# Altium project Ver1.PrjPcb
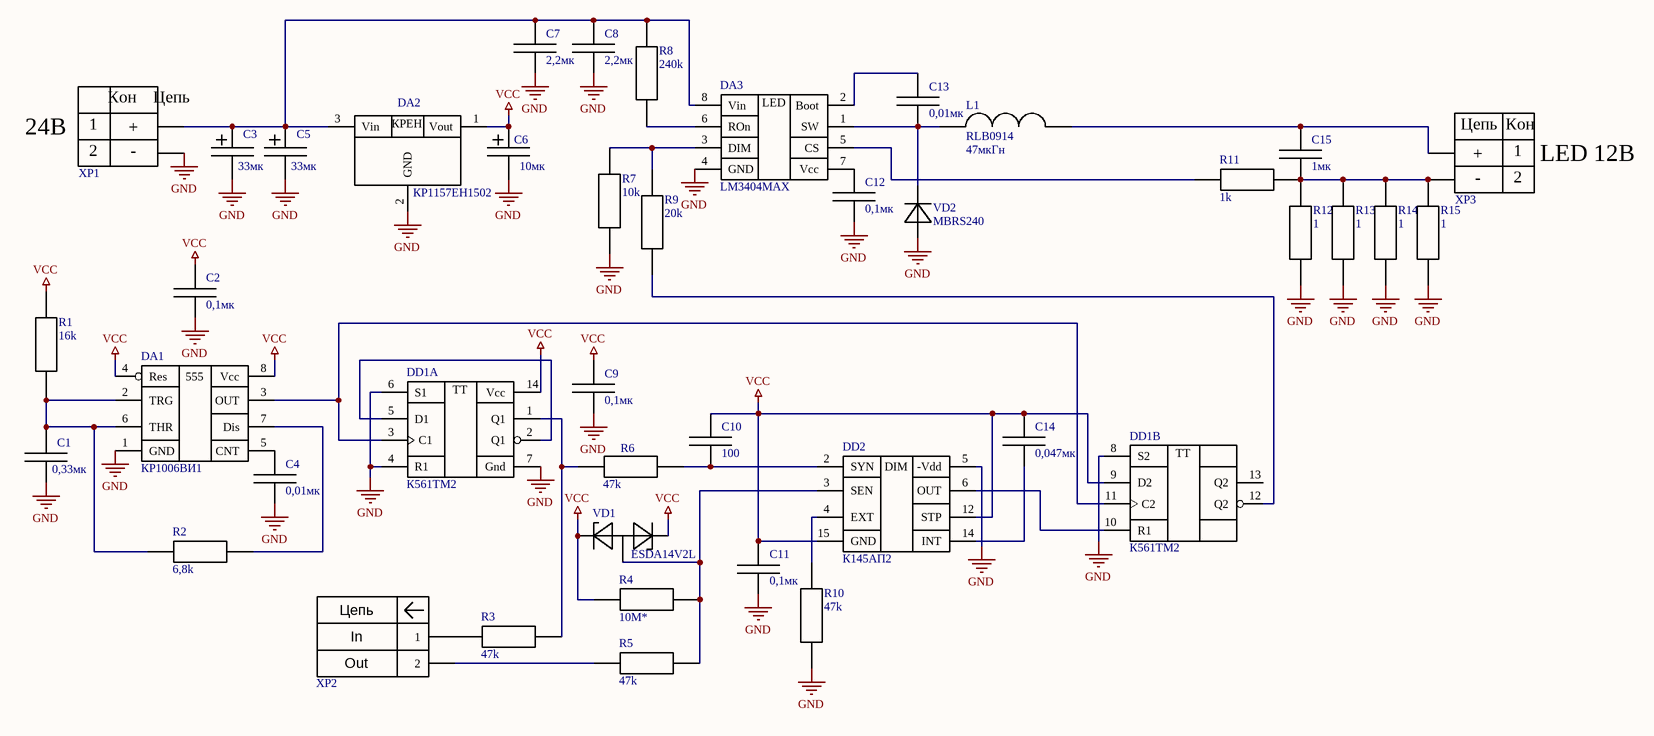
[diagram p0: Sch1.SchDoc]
1 sheet, 41 parts. Net scope: global (net labels, ports and power ports of the same name join across sheets).
Board file: PCB1.PcbDoc

## Sheet Sch1.SchDoc: Наименование
size 420 x 297 mm; ApprovedBy: Утвердил; CheckedBy: Проверил; Author: Разработал; CompanyName: Организация; DocumentNumber: Обозначение; SheetNumber: Лист; SheetTotal: Листов; TechContr: Техн.контр.; NormCotr: Нормоконтроль; DocumentType: Тип документа; InvNumOrigin: Инв № подл; InvNumDuplicate: Инв № дубл; InsteadOfInvNum: Взам. инв. №; RefNumber: Справ. №; InitialUsage: Перв. примен.; Lit: О

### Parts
C1  value 0,33мк  [RC_1206]  (hidden comment: C_1206)
C2  value 0,1мк  [RC_1206]  (hidden comment: C_1206)
C3  value 33мк  [Type D]  (hidden comment: Type D)
C4  value 0,01мк  [RC_1206]  (hidden comment: C_1206)
C5  value 33мк  [Type D]  (hidden comment: Type D)
C6  value 10мк  [Type B]  (hidden comment: Type B)
C7  value 2,2мк  [RC_1206]  (hidden comment: C_1206)
C8  value 2,2мк  [RC_1206]  (hidden comment: C_1206)
C9  value 0,1мк  [RC_1206]  (hidden comment: C_1206)
C10  value 100  [RC_1206]  (hidden comment: C_1206)
C11  value 0,1мк  [RC_1206]  (hidden comment: C_1206)
C12  value 0,1мк  [RC_1206]  (hidden comment: C_1206)
C13  value 0,01мк  [RC_1206]  (hidden comment: C_1206)
C14  value 0,047мк  [RC_1206]  (hidden comment: C_1206)
C15  value 1мк  [RC_1206]  (hidden comment: C_1206)
DA1  КР1006ВИ1  [DIP-8-RU]
DA2  КР1157ЕН1502  [TO-92]
DA3  LM3404MAX  [SO-8]
DD1  К561ТМ2  [DIP-14-RU]  (parts A,B of 2)
DD2  К145АП2  [DIP-16-RU]
L1  RLB0914  value 47мкГн  [RLB0914]
R1  value 16k  [RC_1206]  (hidden comment: R_1206)
R2  value 6,8k  [RC_1206]  (hidden comment: R_1206)
R3  value 47k  [RC_1206]  (hidden comment: R_1206)
R4  value 10M*  [RC_1206]  (hidden comment: R_1206)
R5  value 47k  [RC_1206]  (hidden comment: R_1206)
R6  value 47k  [RC_1206]  (hidden comment: R_1206)
R7  value 10k  [RC_1206]  (hidden comment: R_1206)
R8  value 240k  [RC_1206]  (hidden comment: R_1206)
R9  value 20k  [RC_1206]  (hidden comment: R_1206)
R10  value 47k  [RC_1206]  (hidden comment: R_1206)
R11  value 1k  [RC_1206]  (hidden comment: R_1206)
R12  value 1  [RC_1206]  (hidden comment: R_1206)
R13  value 1  [RC_1206]  (hidden comment: R_1206)
R14  value 1  [RC_1206]  (hidden comment: R_1206)
R15  value 1  [RC_1206]  (hidden comment: R_1206)
VD1  ESDA14V2L  [SOT-23]
VD2  MBRS240  [D-64]
XP1  Power  [2EDGV-2P]  (value not drawn)
XP2  Sensor  [PLS-2]  (value not drawn)
XP3  Power  [2EDGV-2P]  (value not drawn)

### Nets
GND: C1.2 C2.2 C3.2 C4.2 C5.2 C6.2 C7.2 C8.2 C9.2 C11.2 C12.2 DA1.1(GND) DA2.2(GND) DA3.4(GND) DD1.4(R1) DD1.6(S1) DD1.7(Gnd) DD1.8(S2) DD2.5(-Vdd) R7.2 R10.2 R12.1 R13.1 R14.1 R15.1 VD2.1 XP1.2
VCC: C2.1 C6.1 C9.1 C10.1 C11.1 C14.1 DA1.4(Res) DA1.8(Vcc) DA2.1(Vout) DD1.9(D2) DD1.14(Vcc) DD2.12(STP) DD2.15(GND) R1.2 R4.2 VD1.1 VD1.2
NetC1_1: C1.1 DA1.2(TRG) DA1.6(THR) R1.1 R2.2
NetC3_1: C3.1 C5.1 C7.1 C8.1 DA2.3(Vin) DA3.8(Vin) R8.1 XP1.1
NetC4_1: C4.1 DA1.5(CNT)
NetC10_2: C10.2 DD2.2(SYN) R6.1
NetC12_1: C12.1 DA3.7(Vcc)
NetC13_1: C13.1 DA3.2(Boot)
NetC13_2: C13.2 DA3.1(SW) L1.1 VD2.2
NetC14_2: C14.2 DD2.14(INT)
NetC15_1: C15.1 L1.2 XP3.1
NetC15_2: C15.2 R11.1 R12.2 R13.2 R14.2 R15.2 XP3.2
NetDA1_3: DA1.3(OUT) DD1.3(C1) DD1.11(C2)
NetDA1_7: DA1.7(Dis) R2.1
NetDA3_3: DA3.3(DIM) R7.1 R9.2
NetDA3_5: DA3.5(CS) R11.2
NetDA3_6: DA3.6(ROn) R8.2
NetDD1_1: DD1.1(Q1) R3.1 R6.2
NetDD1_2: DD1.2(Q1) DD1.5(D1)
NetDD1_10: DD1.10(R1) DD2.6(OUT)
NetDD1_12: DD1.12(Q2) R9.1
NetDD2_3: DD2.3(SEN) R4.1 R5.1 VD1.3
NetDD2_4: DD2.4(EXT) R10.1
NetR3_2: R3.2 XP2.1
NetR5_2: R5.2 XP2.2

Not connected (* = marked no-connect by the designer): DD1 13(Q2)

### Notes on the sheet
- 24B
- LED 12B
